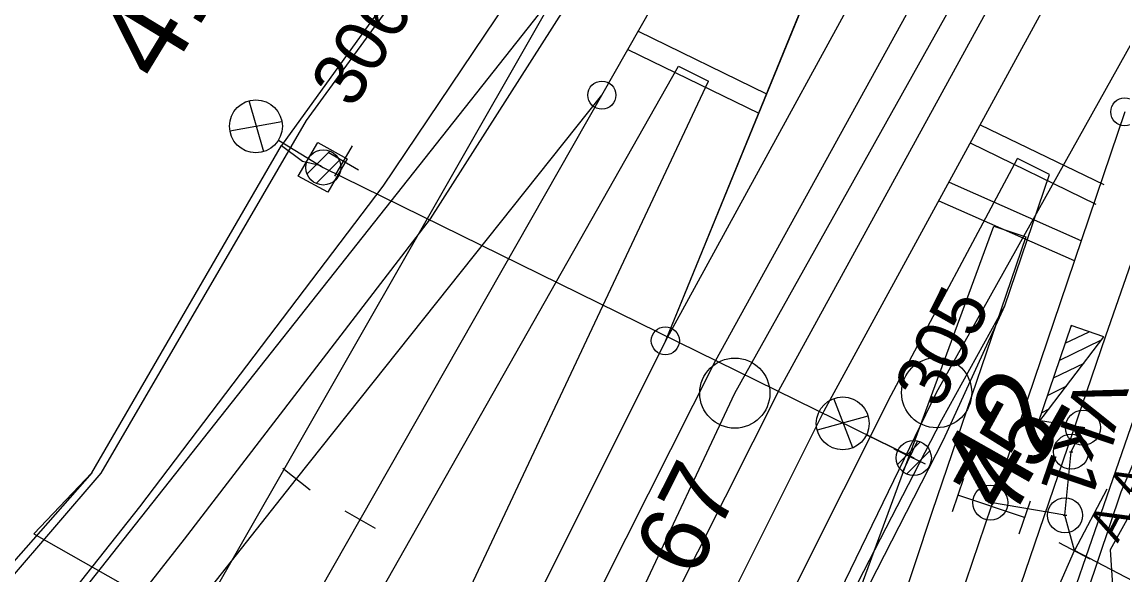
# Model space of a CAD drawing. Extents: x -598638 to -597933, y -1164002 to -1161904.
# Drawn here: x -598211.72 to -598180.34, y -1162941.24 to -1162925.47 of the extents above; entities that cross this region are included whole.
import ezdxf

# ---------------------------------------------------------------- set-up
doc = ezdxf.new("R2010")
doc.units = 0
for name, color, linetype in [('Vrstva 1', 7, 'Continuous'), ('Vrstva 11', 7, 'Continuous'), ('Vrstva 12', 7, 'Continuous'), ('Vrstva 17', 7, 'Continuous'), ('Vrstva 2', 7, 'Continuous'), ('Vrstva 25', 7, 'Continuous'), ('Vrstva 26', 7, 'Continuous'), ('Vrstva 28', 7, 'Continuous'), ('Vrstva 3', 7, 'Continuous'), ('Vrstva 31', 7, 'Continuous'), ('Vrstva 4', 7, 'Continuous'), ('Vrstva 43', 7, 'Continuous'), ('Vrstva 44', 7, 'Continuous'), ('Vrstva 51', 7, 'Continuous'), ('Vrstva 6', 7, 'Continuous'), ('Vrstva 63', 7, 'Continuous'), ('Vrstva 7', 7, 'Continuous')]:
    doc.layers.add(name, color=color, linetype=linetype)

msp = doc.modelspace()

# ---------------------------------------------------------------- linework, layer by layer
at = {"layer": 'Vrstva 1'}
msp.add_line((-598193.375, -1162934.568), (-598187.18, -1162919.408), dxfattribs=at)
for points in [[(-598202.083, -1162939.655), (-598195.19, -1162927.557), (-598187.933, -1162914.793)], [(-598245.185, -1163146.686), (-598244.89, -1163128.996), (-598244.069, -1163113.383), (-598243.892, -1163111.402), (-598242.508, -1163095.903), (-598240.221, -1163078.173), (-598237.7, -1163063), (-598234.456, -1163047.036), (-598230.819, -1163031.867), (-598224.044, -1163008.196), (-598218.147, -1162990.962), (-598212.612, -1162976.381), (-598210.162, -1162970.38), (-598207.127, -1162963.269), (-598201.66, -1162951.286), (-598200.923, -1162949.67), (-598193.375, -1162934.568), (-598185.535, -1162920.228)], [(-598240.169, -1163146.755), (-598239.921, -1163130.309), (-598239.07, -1163113.566), (-598238.926, -1163111.785), (-598238.259, -1163103.539), (-598237.54, -1163096.536), (-598235.247, -1163078.679), (-598233.075, -1163065.413), (-598229.628, -1163048.216), (-598226.08, -1163033.339), (-598219.335, -1163009.739), (-598213.514, -1162992.625), (-598208.094, -1162978.373), (-598205.572, -1162972.188), (-598202.745, -1162965.549), (-598196.38, -1162951.607), (-598188.854, -1162936.558), (-598181.238, -1162922.581)], [(-598203.893, -1162938.499), (-598195.19, -1162927.557)], [(-598180.286, -1162928.035), (-598182.126, -1162933.482), (-598183.238, -1162936.76), (-598184.095, -1162939.282), (-598186.438, -1162946.204), (-598190.315, -1162957.646), (-598194.225, -1162969.204), (-598198.163, -1162980.824), (-598202.116, -1162992.486)], [(-598227.645, -1162968.564), (-598218.383, -1162956.84), (-598218.042, -1162956.408), (-598203.893, -1162938.499)], [(-598206.72, -1162947.797), (-598202.083, -1162939.655)]]:
    msp.add_lwpolyline(points, dxfattribs=at)
msp.add_circle((-598180.286, -1162928.035), 0.4, dxfattribs=at)
at = {"layer": 'Vrstva 11'}
for p, q in [((-598203.591, -1162929.804), (-598202.945, -1162929.158)), ((-598203.331, -1162930.074), (-598202.676, -1162929.419)), ((-598186.761, -1162938.084), (-598186.115, -1162937.438)), ((-598186.501, -1162938.354), (-598185.846, -1162937.699))]:
    msp.add_line(p, q, dxfattribs=at)
msp.add_lwpolyline([(-598203.13, -1162929.62), (-598186.3, -1162937.9)], dxfattribs=at)
for centre in [(-598203.13, -1162929.62), (-598186.3, -1162937.9)]:
    msp.add_circle(centre, 0.5, dxfattribs=at)
at = {"layer": 'Vrstva 12'}
msp.add_lwpolyline([(-598202.45, -1162929.37), (-598203, -1162930.32), (-598203.85, -1162929.87), (-598203.29, -1162928.91), (-598202.45, -1162929.37)], dxfattribs=at)
at = {"layer": 'Vrstva 17'}
msp.add_lwpolyline([(-598160.869, -1162916.03), (-598165.61, -1162912.687), (-598173.226, -1162925.769), (-598179.204, -1162936.08), (-598180.398, -1162938.876), (-598184.227, -1162950.256), (-598188.104, -1162961.627), (-598191.911, -1162973.022), (-598198.535, -1162970.746), (-598204.125, -1162984.71), (-598208.617, -1162995.882), (-598214.208, -1163009.83), (-598215.031, -1163012.689), (-598218.215, -1163027.367), (-598221.453, -1163042.038), (-598223.962, -1163053.782), (-598226.517, -1163065.417), (-598227.975, -1163080.383)], dxfattribs=at)
at = {"layer": 'Vrstva 2'}
for p, q in [((-598204.285, -1162938.189), (-598203.501, -1162938.809)), ((-598202.517, -1162939.408), (-598201.649, -1162939.902))]:
    msp.add_line(p, q, dxfattribs=at)
for points in [[(-598202.083, -1162939.655), (-598195.19, -1162927.557), (-598187.933, -1162914.793)], [(-598193.375, -1162934.568), (-598187.18, -1162919.408)], [(-598200.923, -1162949.67), (-598193.375, -1162934.568), (-598185.535, -1162920.228)], [(-598203.893, -1162938.499), (-598195.19, -1162927.557)]]:
    msp.add_lwpolyline(points, dxfattribs=at)
for centre in [(-598195.191, -1162927.558), (-598193.382, -1162934.561)]:
    msp.add_circle(centre, 0.4, dxfattribs=at)
at = {"layer": 'Vrstva 25'}
for p, q in [((-598205.25, -1162927.715), (-598204.839, -1162929.165)), ((-598205.794, -1162928.572), (-598204.31, -1162928.305)), ((-598204.41, -1162928.837), (-598203.13, -1162929.62)), ((-598188.587, -1162936.198), (-598188.044, -1162937.605)), ((-598189.049, -1162937.102), (-598187.596, -1162936.699)), ((-598187.646, -1162937.238), (-598186.3, -1162937.9)), ((-598181.525, -1162937.037), (-598181.425, -1162937.037)), ((-598181.866, -1162937.725), (-598181.766, -1162937.725)), ((-598184.168, -1162939.174), (-598184.068, -1162939.174)), ((-598182.041, -1162939.535), (-598181.941, -1162939.535))]:
    msp.add_line(p, q, dxfattribs=at)
for centre, radius in [((-598205.05, -1162928.447), 0.754), ((-598188.326, -1162936.916), 0.754), ((-598181.475, -1162937.037), 0.5), ((-598181.816, -1162937.725), 0.5), ((-598184.118, -1162939.174), 0.5), ((-598181.991, -1162939.535), 0.5)]:
    msp.add_circle(centre, radius, dxfattribs=at)
at = {"layer": 'Vrstva 26'}
for points in [[(-598196.526, -1162918.179), (-598204.324, -1162928.997)], [(-598211.382, -1162940.065), (-598209.724, -1162938.321), (-598204.324, -1162928.997)], [(-598204.324, -1162928.997), (-598203.726, -1162929.442), (-598203.189, -1162929.561)], [(-598209.724, -1162938.321), (-598213.637, -1162942.766), (-598224.288, -1162957.992), (-598230.097, -1162966.171)], [(-598211.382, -1162940.065), (-598193.601, -1162950.161), (-598191.584, -1162951.092), (-598198.026, -1162967.205), (-598208.688, -1162993.504), (-598209.03, -1162994.474), (-598214.707, -1163009.33), (-598218.558, -1163024.082), (-598220.34, -1163031.684), (-598220.756, -1163034.417), (-598224.218, -1163049.876), (-598227.646, -1163065.71), (-598228.067, -1163068.213), (-598230.531, -1163097), (-598231.676, -1163107.807), (-598231.723, -1163120.907), (-598232.574, -1163129.537), (-598231.426, -1163150.759)]]:
    msp.add_lwpolyline(points, dxfattribs=at)
at = {"layer": 'Vrstva 28'}
for points in [[(-598165.351, -1162868.56), (-598166.228, -1162870.696), (-598173.183, -1162882.632), (-598174.441, -1162884.858), (-598175.136, -1162886.062), (-598182.344, -1162895.134), (-598182.836, -1162898.802), (-598191.853, -1162911.765), (-598196.365, -1162918.318), (-598203.621, -1162928.284), (-598209.471, -1162938.339), (-598213.445, -1162942.952), (-598224.077, -1162958.183), (-598230.16, -1162966.29)], [(-598181.991, -1162939.535), (-598181.816, -1162937.725), (-598181.475, -1162937.037), (-598183.238, -1162936.76)], [(-598182.85, -1162943.114), (-598181.721, -1162940.54), (-598181.991, -1162939.535), (-598184.118, -1162939.174)]]:
    msp.add_lwpolyline(points, dxfattribs=at)
at = {"layer": 'Vrstva 3'}
for p, q in [((-598181.985, -1162934.626), (-598181.303, -1162934.303)), ((-598181.819, -1162934.137), (-598181.8, -1162934.134)), ((-598182.154, -1162935.123), (-598180.946, -1162934.535)), ((-598182.323, -1162935.62), (-598181.448, -1162935.197)), ((-598182.491, -1162936.117), (-598181.937, -1162935.844)), ((-598182.66, -1162936.614), (-598182.446, -1162936.502)), ((-598184.882, -1162938.488), (-598185.203, -1162939.435)), ((-598183.148, -1162939.603), (-598185.042, -1162938.961)), ((-598182.987, -1162939.129), (-598183.308, -1162940.076))]:
    msp.add_line(p, q, dxfattribs=at)
msp.add_lwpolyline([(-598182.765, -1162936.921), (-598180.879, -1162934.447), (-598181.816, -1162934.129), (-598182.765, -1162936.921)], dxfattribs=at)
msp.add_lwpolyline([(-598182.765, -1162936.921), (-598180.879, -1162934.447), (-598181.816, -1162934.129), (-598182.765, -1162936.921)], dxfattribs=at)
at = {"layer": 'Vrstva 31'}
msp.add_lwpolyline([(-598153.447, -1162881.401), (-598158.917, -1162890.286), (-598163.962, -1162898.735), (-598165.887, -1162906.436), (-598166.192, -1162908.567), (-598166.64, -1162910.14), (-598167.818, -1162914.276), (-598168.011, -1162918.252), (-598168.382, -1162919.355), (-598171.993, -1162924.817), (-598180.701, -1162940.523), (-598180.438, -1162944.574), (-598182.04, -1162949.425), (-598187.501, -1162961.184)], dxfattribs=at)
at = {"layer": 'Vrstva 4'}
for points in [[(-598236.122, -1163097.625), (-598233.737, -1163078.205), (-598231.603, -1163064.919), (-598228.204, -1163048.211), (-598224.742, -1163033.919), (-598217.308, -1163008.105), (-598211.392, -1162991.093), (-598206.621, -1162978.751), (-598200.642, -1162964.474), (-598195.034, -1162952.232), (-598186.946, -1162936.115), (-598183.34, -1162929.36)], [(-598234.285, -1163099.455), (-598231.787, -1163078.342), (-598229.816, -1163067.198), (-598225.948, -1163048.912), (-598222.74, -1163035.209), (-598216.053, -1163011.484), (-598208.869, -1162991.272), (-598204.619, -1162979.312), (-598198.109, -1162964.057), (-598193.443, -1162953.005), (-598185.456, -1162937.387), (-598183.707, -1162933.568)]]:
    msp.add_lwpolyline(points, dxfattribs=at)
at = {"layer": 'Vrstva 43'}
for centre in [(-598191.401, -1162936.053), (-598185.65, -1162936.04)]:
    msp.add_circle(centre, 1, dxfattribs=at)
at = {"layer": 'Vrstva 44'}
for points in [[(-598295.758, -1163493.483), (-598278.118, -1163452.874), (-598264.209, -1163410.565), (-598254.468, -1163367.19), (-598248.62, -1163321.577), (-598253.497, -1163320.887), (-598249.615, -1163272.581), (-598247.635, -1163222.481), (-598247.486, -1163176.779), (-598247.442, -1163130.148), (-598244.014, -1163084.171), (-598235.33, -1163037.762), (-598224.817, -1163002.559), (-598219.379, -1163002.169), (-598206.652, -1162968.487), (-598191.401, -1162936.053), (-598173.754, -1162904.506), (-598155.689, -1162873.083), (-598136.14, -1162838.446), (-598116.776, -1162804.197)], [(-598214.433, -1163003.397), (-598199.219, -1162964.022), (-598185.65, -1162936.04), (-598163.291, -1162895.981), (-598150.219, -1162876.092), (-598140.441, -1162856.726), (-598110.998, -1162804.439)], [(-598217.579, -1162951.29), (-598196.167, -1162924.209), (-598178.917, -1162893.572), (-598182.378, -1162891.173)]]:
    msp.add_lwpolyline(points, dxfattribs=at)
at = {"layer": 'Vrstva 51'}
for points in [[(-598243.76, -1163139.382), (-598243.393, -1163128.836), (-598242.662, -1163113.52), (-598241.121, -1163096.732), (-598238.542, -1163077.297), (-598236.364, -1163063.881), (-598233.006, -1163047.35), (-598229.452, -1163032.186), (-598222.566, -1163008.635), (-598216.788, -1162991.447), (-598211.314, -1162977.141), (-598198.954, -1162949.031), (-598191.954, -1162935.136), (-598181.215, -1162915.654), (-598172.367, -1162900.092), (-598146.639, -1162854.694), (-598125.435, -1162817.431), (-598123.403, -1162813.873), (-598093.874, -1162762.323), (-598071.494, -1162722.83), (-598058.726, -1162701.732), (-598043.403, -1162678.606), (-598026.165, -1162652.845)], [(-598239.095, -1163097.092), (-598236.576, -1163077.501), (-598234.309, -1163064.254), (-598231.064, -1163047.867), (-598227.331, -1163032.522), (-598220.677, -1163009.309), (-598214.847, -1162992.197), (-598209.449, -1162977.846), (-598197.189, -1162949.981), (-598190.09, -1162935.876), (-598179.544, -1162916.618), (-598170.666, -1162900.915), (-598144.793, -1162855.5), (-598123.538, -1162818.503), (-598121.573, -1162814.996), (-598092.208, -1162763.361), (-598069.503, -1162724.253), (-598055.71, -1162703.114), (-598040.468, -1162680.627), (-598023.352, -1162655.056), (-598026.165, -1162652.845)], [(-598247.161, -1162992.683), (-598248.445, -1162991.682), (-598236.167, -1162974.65), (-598221.601, -1162956.026), (-598208.36, -1162939.293), (-598201.425, -1162930.155), (-598189.853, -1162912.957), (-598180.619, -1162896.952), (-598175.616, -1162888.402), (-598174.501, -1162888.256)], [(-598247.161, -1162992.683), (-598234.984, -1162975.74), (-598220.234, -1162956.982), (-598207.085, -1162940.213), (-598200.076, -1162931.081), (-598188.898, -1162913.557), (-598179.448, -1162896.986), (-598174.501, -1162888.256)], [(-598221.478, -1163080.78), (-598219.566, -1163067.136), (-598219.219, -1163065.098), (-598216.814, -1163053.054), (-598216.308, -1163050.154), (-598213.455, -1163037.18), (-598209.254, -1163020.993), (-598206.671, -1163012.257), (-598205.894, -1163009.286), (-598205.807, -1163008.944), (-598201.906, -1162996.551), (-598193.548, -1162971.953), (-598188.761, -1162957.834), (-598185.003, -1162946.673), (-598180.831, -1162934.422), (-598177.192, -1162923.967), (-598173.595, -1162914.671), (-598168.64, -1162904.115), (-598164.118, -1162895.651), (-598162.659, -1162896.444)], [(-598162.659, -1162896.444), (-598167.315, -1162905.247), (-598172.294, -1162915.543), (-598175.907, -1162924.588), (-598179.431, -1162935.039), (-598183.642, -1162947.197), (-598187.437, -1162958.573), (-598192.02, -1162972.557), (-598198.809, -1162992.788), (-598204.748, -1163011.314), (-598205.213, -1163012.907), (-598207.438, -1163020.452), (-598209.822, -1163028.442), (-598211.787, -1163036.541), (-598212.573, -1163039.781), (-598214.64, -1163049.347), (-598215.473, -1163053.325), (-598217.705, -1163064.512), (-598218.096, -1163067.37), (-598220.007, -1163080.081)], [(-598209.837, -1162956.862), (-598203.604, -1162945.446), (-598193.004, -1162926.731), (-598192.155, -1162927.156)], [(-598244.076, -1163096.672), (-598241.475, -1163076.865), (-598239.091, -1163062.576), (-598235.906, -1163046.679), (-598232.162, -1163031.147), (-598225.436, -1163007.609), (-598219.516, -1162990.586), (-598213.911, -1162975.868), (-598206.637, -1162958.627), (-598201.26, -1162946.534), (-598192.155, -1162927.156)], [(-598234.985, -1163097.818), (-598232.528, -1163078.41), (-598230.539, -1163066.595), (-598226.731, -1163048.661), (-598223.587, -1163035.053), (-598216.724, -1163011.435), (-598209.696, -1162991.235), (-598205.138, -1162979.218), (-598199.051, -1162964.673), (-598193.758, -1162952.835), (-598185.502, -1162936.812), (-598183.707, -1162933.568), (-598182.431, -1162929.818), (-598183.34, -1162929.36)], [(-598225.987, -1163079.977), (-598225.433, -1163075.24), (-598224.4, -1163068.446), (-598223.276, -1163062.974), (-598221.56, -1163053.654), (-598219.088, -1163041.864), (-598218.289, -1163038.506), (-598215.72, -1163028.247), (-598212.289, -1163016.175), (-598208.971, -1163004.649), (-598206.367, -1162996.288), (-598201.674, -1162982.251), (-598196.929, -1162967.908), (-598191.009, -1162950.285), (-598184.021, -1162931.293), (-598183.109, -1162931.599)], [(-598183.109, -1162931.599), (-598185.779, -1162939.427), (-598189.427, -1162950.443), (-598195.6, -1162968.473), (-598201.203, -1162984.962), (-598205.181, -1162996.978), (-598207.823, -1163005.387), (-598207.873, -1163005.495), (-598211.27, -1163016.966), (-598211.421, -1163017.483), (-598214.449, -1163028.785), (-598217.013, -1163039.126), (-598217.753, -1163042.541), (-598220.273, -1163054.386), (-598221.987, -1163063.395), (-598223.013, -1163069.069), (-598224.075, -1163075.616), (-598224.553, -1163080.356)]]:
    msp.add_lwpolyline(points, dxfattribs=at)
at = {"layer": 'Vrstva 6'}
for p, q in [((-598180.799, -1162938.788), (-598181.721, -1162940.54)), ((-598182.163, -1162940.307), (-598181.279, -1162940.773)), ((-598146.315, -1162959.151), (-598181.721, -1162940.54))]:
    msp.add_line(p, q, dxfattribs=at)
at = {"layer": 'Vrstva 63'}
msp.add_line((-598215.837, -1162958.494), (-598115.28, -1162782.61), dxfattribs=at)
at = {"layer": 'Vrstva 7'}
for p, q in [((-598194.155, -1162925.737), (-598190.494, -1162927.517)), ((-598194.453, -1162926.26), (-598190.721, -1162928.074)), ((-598184.413, -1162928.408), (-598180.882, -1162930.11)), ((-598202.307, -1162929.001), (-598202.809, -1162929.865)), ((-598184.69, -1162928.916), (-598181.109, -1162930.667)), ((-598202.99, -1162929.182), (-598202.126, -1162929.684)), ((-598181.529, -1162931.714), (-598185.286, -1162930.05)), ((-598181.722, -1162932.285), (-598185.579, -1162930.576)), ((-598186.195, -1162937.415), (-598186.629, -1162938.315)), ((-598185.962, -1162938.082), (-598186.862, -1162937.648))]:
    msp.add_line(p, q, dxfattribs=at)

# ---------------------------------------------------------------- texts
at = {"layer": 'Vrstva 11'}
for s, rotation, p in [('41', 58.6525, (-598207.703, -1162927.304)), ('42', 60.5196, (-598183.591, -1162939.594))]:
    msp.add_text(s, height=2.5, rotation=rotation, dxfattribs=at).set_placement(p)
at = {"layer": 'Vrstva 25'}
for s, rotation, p in [('306', 58.5433, (-598202.283, -1162927.981)), ('305', 63.8275, (-598185.566, -1162936.544))]:
    msp.add_text(s, height=1.5, rotation=rotation, dxfattribs=at).set_placement(p)
at = {"layer": 'Vrstva 3'}
msp.add_text('Vk1', height=1.5, rotation=251.2317, dxfattribs=at).set_placement((-598181.583, -1162935.454))
at = {"layer": 'Vrstva 43'}
for s, rotation, p in [('75', 61.4142, (-598183.489, -1162939.644)), ('67', 63.262, (-598192.554, -1162941.386))]:
    msp.add_text(s, height=2, rotation=rotation, dxfattribs=at).set_placement(p)
at = {"layer": 'Vrstva 6'}
msp.add_text('  A A', height=1, rotation=62.2713, dxfattribs=at).set_placement((-598180.835, -1162941.005))

doc.saveas('drawing.dxf')
